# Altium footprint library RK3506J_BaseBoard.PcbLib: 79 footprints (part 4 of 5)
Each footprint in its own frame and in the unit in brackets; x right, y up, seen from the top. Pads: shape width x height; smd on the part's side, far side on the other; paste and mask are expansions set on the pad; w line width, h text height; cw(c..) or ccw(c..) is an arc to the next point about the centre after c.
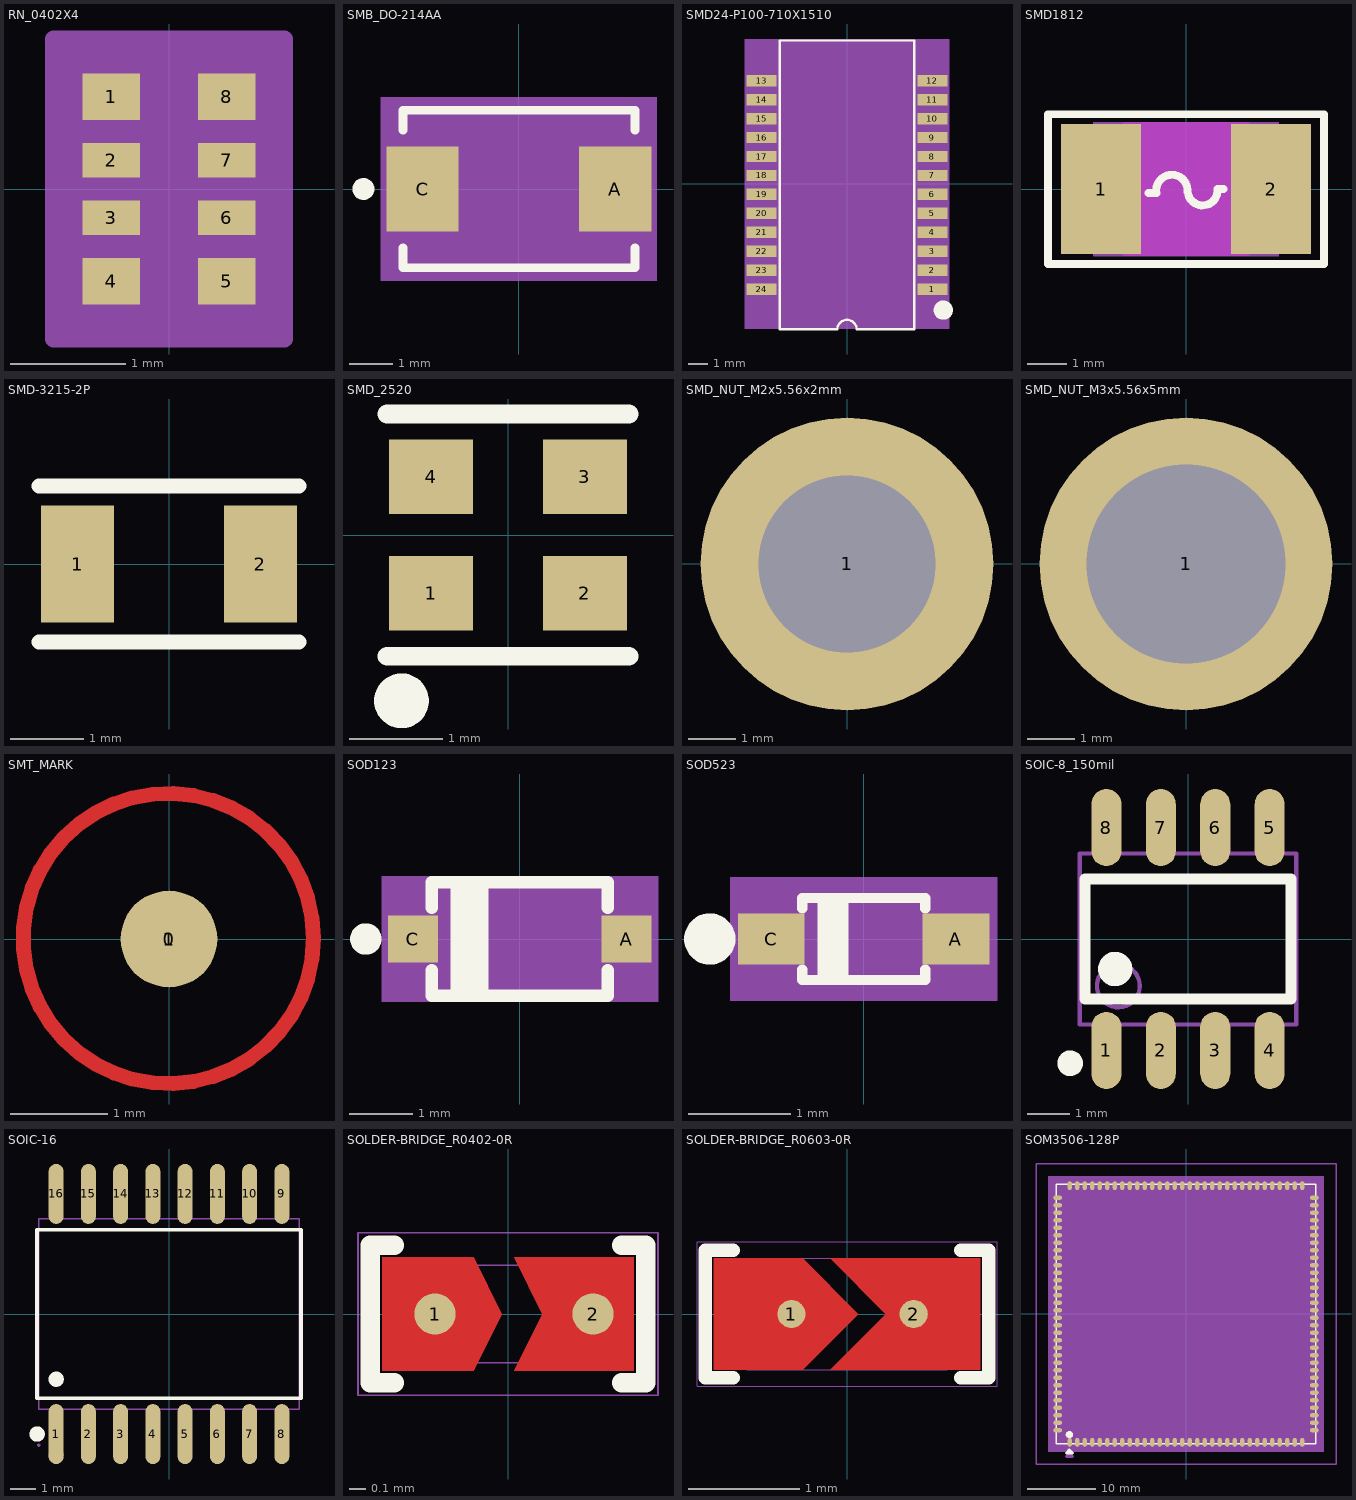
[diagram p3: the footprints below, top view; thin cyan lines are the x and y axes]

## RN_0402X4 [mm]
pads (8):
  rect 0.5x0.4 smd: 1(-0.5,0.8) 4(-0.5,-0.8) 5(0.5,-0.8) 8(0.5,0.8)
  rect 0.5x0.3 smd: 2(-0.5,0.25) 3(-0.5,-0.25) 6(0.5,-0.25) 7(0.5,0.25)
Top 3D Body:
  region: -1,1.3 -1,-1.3 1,-1.3 1,1.3
Top Assembly:
  lines w0.15: -1,-1.3 -1,1.3 1,1.3 1,-1.3 -1,-1.3
Top Courtyard:
  dashed: -1,1.3 -1,-1.3 1,-1.3 1,1.3
Mechanical 15:
  text "3" at -0.246,-0.25 h0.76
  text "1" at -0.246,0.8 h0.76
  text "4" at -0.246,-0.8 h0.76
  text "2" at -0.246,0.25 h0.76
  text "5" at 0.754,-0.8 h0.76
  text "8" at 0.754,0.8 h0.76
  text "6" at 0.754,-0.25 h0.76
  text "7" at 0.754,0.25 h0.76
3D body: height 3.81, standoff 0, extent -1,-1.3 1,1.3

## SMB_DO-214AA [mm]
pads (2):
  rect 1.65x1.95 smd: A(2.2,0) C(-2.2,0)
Top Overlay:
  circle w0.25: c-3.55,0 r0.125
  lines w0.2: -2.65,-1.35 -2.65,-1.8 2.65,-1.8 2.65,-1.35 ; -2.65,1.35 -2.65,1.8 2.65,1.8 2.65,1.35
Top 3D Body:
  circle w0.05: c0,0 r0.35
  region: -3.15,-2.1 -3.15,2.1 3.15,2.1 3.15,-2.1
  lines w0.05: -0.5,0 0.5,0 ; 0,-0.5 0,0.5
Top Assembly:
  lines w0.1: -2.568,-1.81 -2.568,1.81 ; -2.468,-1.81 -2.468,1.81 ; -2.368,-1.81 -2.368,1.81 ; -2.268,-1.81 -2.268,1.81 ; -2.168,-1.81 -2.168,1.81 ; -2.068,-1.81 -2.068,1.81 ; -1.968,-1.81 -1.968,1.81 ; -2.668,-1.81 -2.668,1.81 2.668,1.81 2.668,-1.81 -2.668,-1.81
Top Component Outline:
  lines w0.001: -2.795,-1.97 -2.795,1.97 2.795,1.97 2.795,-1.97 -2.795,-1.97
Top Courtyard:
  dashed: -3.15,-2.1 -3.15,2.1 3.15,2.1 3.15,-2.1
Mechanical 15:
  text "C" at -2.2,0.254 h0.76
  text "A" at 2.2,0.254 h0.76
3D body: height 3.81, standoff 0, extent -3.15,-2.1 3.15,2.1

## SMD24-P100-710X1510 [mm]
pads (24):
  rect 1.6x0.6 smd: 1(4.51,-5.55) 2(4.51,-4.55) 3(4.51,-3.55) 4(4.51,-2.55) 5(4.51,-1.55) 6(4.51,-0.55) 7(4.51,0.45) 8(4.51,1.45) 9(4.51,2.45) 10(4.51,3.45) 11(4.51,4.45) 12(4.51,5.45) 13(-4.51,5.45) 14(-4.51,4.45) 15(-4.51,3.45) 16(-4.51,2.45) 17(-4.51,1.45) 18(-4.51,0.45) 19(-4.51,-0.55) 20(-4.51,-1.55) 21(-4.51,-2.55) 22(-4.51,-3.55) 23(-4.51,-4.55) 24(-4.51,-5.55)
Top Overlay:
  circle w0.508: c5.08,-6.654 r0.254
  lines w0.127: -3.556,-7.67 -3.556,7.57 3.556,7.57 3.556,-7.67 0.508,-7.67 ccw(c0,-7.67) -0.508,-7.67 -3.556,-7.67
Top 3D Body:
  region: -5.4,-7.65 -5.4,7.65 5.4,7.65 5.4,-7.65
Top Assembly:
  circle w0.152: c2.794,-5.663 r0.402
  lines w0.051: -5,-7.6 -5,7.5 5,7.5 5,-7.6 -5,-7.6
Top Component Center:
  lines w0.051: -0.508,-0.05 0.508,-0.05 ; 0,-0.558 0,0.458
Mechanical 15:
  text "13" at -4.51,5.247 h0.25
  text "18" at -4.51,0.247 h0.25
  text "16" at -4.51,2.247 h0.25
  text "21" at -4.51,-2.753 h0.25
  text "22" at -4.51,-3.753 h0.25
  text "15" at -4.51,3.247 h0.25
  text "20" at -4.51,-1.753 h0.25
  text "19" at -4.51,-0.753 h0.25
  text "14" at -4.51,4.247 h0.25
  text "24" at -4.51,-5.753 h0.25
  text "23" at -4.51,-4.753 h0.25
  text "17" at -4.51,1.247 h0.25
  text "8" at 4.51,1.349 h0.25
  text "9" at 4.51,2.349 h0.25
  text "11" at 4.51,4.247 h0.25
  text "12" at 4.51,5.247 h0.25
  text "2" at 4.51,-4.652 h0.25
  text "3" at 4.51,-3.652 h0.25
  text "5" at 4.51,-1.652 h0.25
  text "6" at 4.51,-0.652 h0.25
  text "4" at 4.51,-2.652 h0.25
  text "10" at 4.51,3.247 h0.25
  text "1" at 4.51,-5.652 h0.25
  text "7" at 4.51,0.349 h0.25
3D body: height 3.81, standoff 0, extent -5.4,-7.65 5.4,7.65

## SMD1812 [mil]
pads (2):
  rect 80x130 smd: 1(-85,0) 2(85,0)
Top Layer keep-out:
  region: -63,66.9 -63,-66.9 63,-66.9 63,66.9
Top Overlay:
  lines w7.9: -37.4,-3.9 -29.5,-3.9 cw(c-14.1,-1.36) 1.5,-1.5 ; 1.6,-0.6 ccw(c16.57,-1.37) 31.5,0 37.4,0 ; -137.8,-74.8 -137.8,74.8 137.8,74.8 137.8,-74.8 -137.8,-74.8
Top 3D Body:
  region: -92.5,-66.9 -92.5,66.9 92.5,66.9 92.5,-66.9
Top Assembly:
  lines w1: -88.6,-63 -88.6,63 88.6,63 88.6,-63 -88.6,-63
Top Courtyard:
  lines w1: -92.5,-66.9 92.5,-66.9 92.5,66.9 -92.5,66.9 -92.5,-66.9
Top Component Center:
  lines w3: -20,0 20,0 ; 0,-20 0,20
Mechanical 15:
  text "1" at -95,0 h30
  text "2" at 75,0 h30
3D body: height 150, standoff 0, extent -92.5,-66.9 92.5,66.9

## SMD-3215-2P [mm]
pads (2):
  rect 1x1.6 smd mask+0.051: 1(-1.25,0) 2(1.25,0)
Top Overlay:
  lines w0.203: -1.778,-1.067 1.778,-1.067 ; -1.778,1.067 1.778,1.067

## SMD_2520 [mm]
pads (4):
  rect 0.9x0.8 smd: 1(-0.825,-0.625) 2(0.825,-0.625) 3(0.825,0.625) 4(-0.825,0.625)
Top Overlay:
  circle w0.305: c-1.143,-1.778 r0.141
  lines w0.203: -1.3,-1.3 1.3,-1.3 ; -1.3,1.3 1.3,1.3

## SMD_NUT_M2x5.56x2mm [mm]
pads (1):
  round 6.2 hole 3.75 mask+0.102: 1(0,0)
Top Paste:
  region: -1.097,1.803 -0.971,1.873 -0.707,1.988 -0.43,2.066 -0.144,2.105 0.144,2.105 0.429,2.066 0.706,1.988 0.97,1.874 1.096,1.803 1.862,2.569 1.863,2.571 1.661,2.717 1.217,2.943 0.742,3.097 0.249,3.175 -0.25,3.175 -0.742,3.097 -1.217,2.943 -1.662,2.717 -1.863,2.571
  region: 1.803,1.097 1.873,0.971 1.988,0.707 2.066,0.43 2.105,0.144 2.105,-0.144 2.066,-0.429 1.988,-0.706 1.874,-0.97 1.803,-1.096 2.569,-1.862 2.571,-1.863 2.717,-1.661 2.943,-1.217 3.097,-0.742 3.175,-0.249 3.175,0.25 3.097,0.742 2.943,1.217 2.717,1.662 2.571,1.863
  region: 1.097,-1.803 0.971,-1.873 0.707,-1.988 0.43,-2.066 0.144,-2.105 -0.144,-2.105 -0.429,-2.066 -0.706,-1.988 -0.97,-1.874 -1.096,-1.803 -1.862,-2.569 -1.863,-2.571 -1.661,-2.717 -1.217,-2.943 -0.742,-3.097 -0.249,-3.175 0.25,-3.175 0.742,-3.097 1.217,-2.943 1.662,-2.717 1.863,-2.571
  region: -1.803,-1.097 -1.873,-0.971 -1.988,-0.707 -2.066,-0.43 -2.105,-0.144 -2.105,0.144 -2.066,0.429 -1.988,0.706 -1.874,0.97 -1.803,1.096 -2.569,1.862 -2.571,1.863 -2.717,1.661 -2.943,1.217 -3.097,0.742 -3.175,0.249 -3.175,-0.25 -3.097,-0.742 -2.943,-1.217 -2.717,-1.662 -2.571,-1.863

## SMD_NUT_M3x5.56x5mm [mm]
pads (1):
  round 6.2 / inner round 5 / far side round 6.2 hole 4.22 mask+0.102: 1(0,0)
Top Paste:
  region: -1.097,1.803 -0.971,1.873 -0.707,1.988 -0.43,2.066 -0.144,2.105 0.144,2.105 0.429,2.066 0.706,1.988 0.97,1.874 1.096,1.803 1.862,2.569 1.863,2.571 1.661,2.717 1.217,2.943 0.742,3.097 0.249,3.175 -0.25,3.175 -0.742,3.097 -1.217,2.943 -1.662,2.717 -1.863,2.571
  region: 1.803,1.097 1.873,0.971 1.988,0.707 2.066,0.43 2.105,0.144 2.105,-0.144 2.066,-0.429 1.988,-0.706 1.874,-0.97 1.803,-1.096 2.569,-1.862 2.571,-1.863 2.717,-1.661 2.943,-1.217 3.097,-0.742 3.175,-0.249 3.175,0.25 3.097,0.742 2.943,1.217 2.717,1.662 2.571,1.863
  region: 1.097,-1.803 0.971,-1.873 0.707,-1.988 0.43,-2.066 0.144,-2.105 -0.144,-2.105 -0.429,-2.066 -0.706,-1.988 -0.97,-1.874 -1.096,-1.803 -1.862,-2.569 -1.863,-2.571 -1.661,-2.717 -1.217,-2.943 -0.742,-3.097 -0.249,-3.175 0.25,-3.175 0.742,-3.097 1.217,-2.943 1.662,-2.717 1.863,-2.571
  region: -1.803,-1.097 -1.873,-0.971 -1.988,-0.707 -2.066,-0.43 -2.105,-0.144 -2.105,0.144 -2.066,0.429 -1.988,0.706 -1.874,0.97 -1.803,1.096 -2.569,1.862 -2.571,1.863 -2.717,1.661 -2.943,1.217 -3.097,0.742 -3.175,0.249 -3.175,-0.25 -3.097,-0.742 -2.943,-1.217 -2.717,-1.662 -2.571,-1.863

## SMT_MARK [mm]
pads (2):
  round 3.1 on Top Solder: 0(0,0)
  round 1 smd: 1(0,0)
Top Layer:
  circle w0.152: c-0.007,0.005 r1.5

## SOD123 [mm]
pads (2):
  rect 0.8x0.75 smd: A(1.7,0) C(-1.7,0)
Top Overlay:
  circle w0.25: c-2.45,0 r0.125
  lines w0.2: -1.4,-0.5 -1.4,-0.9 1.4,-0.9 1.4,-0.5 ; -1.4,0.5 -1.4,0.9 1.4,0.9 1.4,0.5 ; -1,-0.8 -1,0.8 ; -0.8,-0.8 -0.8,0.8 ; -0.6,-0.8 -0.6,0.8
Top 3D Body:
  circle w0.05: c0,0 r0.35
  region: -2.2,-1 -2.2,1 2.2,1 2.2,-1
  lines w0.05: -0.5,0 0.5,0 ; 0,-0.5 0,0.5
Top Assembly:
  lines w0.1: -1.25,-0.8 -1.25,0.8 ; -1.15,-0.8 -1.15,0.8 ; -1.05,-0.8 -1.05,0.8 ; -0.95,-0.8 -0.95,0.8 ; -0.85,-0.8 -0.85,0.8 ; -0.75,-0.8 -0.75,0.8 ; -0.65,-0.8 -0.65,0.8 ; -1.35,-0.8 1.35,-0.8 1.35,0.8 -1.35,0.8 -1.35,-0.8
  text ".Designator" at -0.046,0.254 h0.36
Top Component Outline:
  lines w0.001: -1.425,-0.9 1.425,-0.9 1.425,0.9 -1.425,0.9 -1.425,-0.9
Top Courtyard:
  dashed: -2.2,-1 -2.2,1 2.2,1 2.2,-1
Mechanical 15:
  text "C" at -1.954,0 h0.64
  text "A" at 1.446,0 h0.64
3D body: height 3.81, standoff 0, extent -2.2,-1 2.2,1

## SOD523 [mm]
pads (2):
  rect 0.65x0.5 smd: A(0.9,0) C(-0.9,0)
Top Overlay:
  circle w0.25: c-1.5,0 r0.125
  lines w0.1: -0.6,-0.3 -0.6,-0.4 0.6,-0.4 0.6,-0.3 ; -0.6,0.3 -0.6,0.4 0.6,0.4 0.6,0.3 ; -0.4,-0.4 -0.4,0.4 ; -0.3,-0.4 -0.3,0.4 ; -0.2,-0.4 -0.2,0.4
Top 3D Body:
  circle w0.05: c0,0 r0.35
  region: -1.3,0.6 -1.3,-0.6 1.3,-0.6 1.3,0.6
  lines w0.05: -0.5,0 0.5,0 ; 0,-0.5 0,0.5
Top Assembly:
  lines w0.1: -0.475,-0.4 -0.475,0.4 ; -0.375,-0.4 -0.375,0.4 ; -0.275,-0.4 -0.275,0.4 ; -0.175,-0.4 -0.175,0.4 ; -0.075,-0.4 -0.075,0.4 ; -0.575,-0.4 0.575,-0.4 0.575,0.4 -0.575,0.4 -0.575,-0.4
  text ".Designator" at 0,-0.681 h0.36
Top Component Outline:
  lines w0.001: -0.6,-0.425 0.6,-0.425 0.6,0.425 -0.6,0.425 -0.6,-0.425
Mechanical 15:
  text "A" at 0.9,-0.254 h0.64
  text "C" at -0.9,-0.254 h0.64
3D body: height 3.81, standoff 0, extent -1.3,-0.6 1.3,0.6

## SOIC-8_150mil [mm]
pads (8):
  oval 0.7x1.8 smd: 1(-1.905,-2.6) 2(-0.635,-2.6) 3(0.635,-2.6) 4(1.905,-2.6) 5(1.905,2.6) 6(0.635,2.6) 7(-0.635,2.6) 8(-1.905,2.6)
Top Overlay:
  circle w0.4: c-1.7,-0.7 r0.2
  circle w0.3: c-2.75,-2.9 r0.15
  lines w0.254: -2.4,-1.4 -2.4,1.4 2.4,1.4 2.4,-1.4 -2.4,-1.4
Mechanical 13:
  circle w0.1: c-1.625,-1.095 r0.5
  lines w0.1: -2.525,-1.995 -2.525,1.995 2.525,1.995 2.525,-1.995 -2.525,-1.995

## SOIC-16 [mm]
pads (16):
  oval 0.595x2.36 smd: 1(-4.445,-4.73) 2(-3.175,-4.73) 3(-1.905,-4.73) 4(-0.635,-4.73) 5(0.635,-4.73) 6(1.905,-4.73) 7(3.175,-4.73) 8(4.445,-4.73) 9(4.445,4.73) 10(3.175,4.73) 11(1.905,4.73) 12(0.635,4.73) 13(-0.635,4.73) 14(-1.905,4.73) 15(-3.175,4.73) 16(-4.445,4.73)
Top Overlay:
  circle w0.3: c-4.445,-2.569 r0.15
  circle w0.3: c-5.195,-4.73 r0.15
  lines w0.152: -5.206,-3.321 -5.206,3.321 5.206,3.321 5.206,-3.321 -5.206,-3.321
Top Component Outline:
  circle w0.3: c-4.445,-5.563 r0.15
Mechanical 15:
  drawing of 37 lines, arcs and shapes, not listed

## SOLDER-BRIDGE_R0402-0R [mil]
pads (2):
  round 10 smd paste-393.7: 1(-17.72,0) 2(20.67,0)
Top Layer:
  region: -30.51,-13.78 -30.51,13.78 -8.37,13.78 -1.48,0 -8.37,-13.78
  region: 1.48,13.78 8.37,0 1.48,-13.78 30.51,-13.78 30.51,13.78
Top Overlay:
  lines w4.72: -27.56,-16.73 -33.46,-16.73 -33.46,16.73 -27.56,16.73 ; 27.56,-16.73 33.46,-16.73 33.46,16.73 27.56,16.73
Top Paste:
  rectangle: -27.56,-13.78 -8.37,13.78
  rectangle: 8.36,-13.78 27.55,13.78
Top Solder:
  region: -29.53,15.75 -6.4,15.75 1.48,0 -6.4,-15.75 -29.53,-15.75
  region: 5.41,0 -2.46,15.75 29.53,15.75 29.53,-15.75 -2.46,-15.75
Mechanical 14:
  lines w0.39: -17.72,-11.81 -17.72,11.81 17.72,11.81 17.72,-11.81 -17.72,-11.81
  text "'.Designator'" at -78.74,-19.68 h29.53
Mechanical 16:
  lines w0.39: -36.42,-19.68 -36.42,19.68 36.42,19.68 36.42,-19.68 -36.42,-19.68
3D body "R0402.STEP": height 13.39, standoff 0, extent -20.47,-11.81 20.47,11.81
3D body: height 13.78, standoff 0, extent -17.72,-11.81 17.72,11.81

## SOLDER-BRIDGE_R0603-0R [mil]
pads (2):
  round 10 smd paste-393.7: 1(-19.68,0) 2(23.62,0)
Top Layer:
  region: -47.24,-19.68 -47.24,19.68 -15.75,19.68 3.94,0 -15.75,-19.68
  region: -5.91,19.68 13.78,0 -5.91,-19.68 47.24,-19.68 47.24,19.68
Top Overlay:
  lines w4.72: -40.35,-22.64 -50.2,-22.64 -50.2,6.89 -50.2,22.64 -40.35,22.64 ; 40.35,-22.64 50.2,-22.64 50.2,22.64 40.35,22.64
Top Paste:
  rectangle: 14.96,-19.68 40.16,19.68
  rectangle: -40.16,-19.68 -14.96,19.69
Top Solder:
  region: -42.32,21.65 -14.76,21.65 6.89,0 -14.76,-21.65 -42.32,-21.65
  region: 10.83,0 -10.83,21.65 42.32,21.65 42.32,-21.65 -10.83,-21.65
Mechanical 14:
  lines w0.39: -35.43,-19.68 -35.43,19.68 35.43,19.68 35.43,-19.68 -35.43,-19.68
  text "'.Designator'" at -78.74,-19.68 h29.53
Mechanical 16:
  lines w0.39: -53.15,-25.59 -53.15,25.59 -7.87,25.59 53.15,25.59 53.15,-25.59 -53.15,-25.59
3D body "R0603.STEP": height 22.05, standoff 0, extent -33.46,-15.74 33.47,15.75
3D body: height 19.68, standoff 0, extent -35.63,-19.88 35.63,19.88

## SOM3506-128P [mm]
pads (128):
  oval 0.66x1.27 smd: 1(-17.05,-18.835) 2(-15.95,-18.835) 3(-14.85,-18.835) 4(-13.75,-18.835) 5(-12.65,-18.835) 6(-11.55,-18.835) 7(-10.45,-18.835) 8(-9.35,-18.835) 9(-8.25,-18.835) 10(-7.15,-18.835) 11(-6.05,-18.835) 12(-4.95,-18.835) 13(-3.85,-18.835) 14(-2.75,-18.835) 15(-1.65,-18.835) 16(-0.55,-18.835) 17(0.55,-18.835) 18(1.65,-18.835) 19(2.75,-18.835) 20(3.85,-18.835) 21(4.95,-18.835) 22(6.05,-18.835) 23(7.15,-18.835) 24(8.25,-18.835) 25(9.35,-18.835) 26(10.45,-18.835) 27(11.55,-18.835) 28(12.65,-18.835) 29(13.75,-18.835) 30(14.85,-18.835) 31(15.95,-18.835) 32(17.05,-18.835) 65(17.05,18.835) 66(15.95,18.835) 67(14.85,18.835) 68(13.75,18.835) 69(12.65,18.835) 70(11.55,18.835) 71(10.45,18.835) 72(9.35,18.835) 73(8.25,18.835) 74(7.15,18.835) 75(6.05,18.835) 76(4.95,18.835) 77(3.85,18.835) 78(2.75,18.835) 79(1.65,18.835) 80(0.55,18.835) 81(-0.55,18.835) 82(-1.65,18.835) 83(-2.75,18.835) 84(-3.85,18.835) 85(-4.95,18.835) 86(-6.05,18.835) 87(-7.15,18.835) 88(-8.25,18.835) 89(-9.35,18.835) 90(-10.45,18.835) 91(-11.55,18.835) 92(-12.65,18.835) 93(-13.75,18.835) 94(-14.85,18.835) 95(-15.95,18.835) 96(-17.05,18.835)
  oval 1.27x0.66 smd: 33(18.835,-17.05) 34(18.835,-15.95) 35(18.835,-14.85) 36(18.835,-13.75) 37(18.835,-12.65) 38(18.835,-11.55) 39(18.835,-10.45) 40(18.835,-9.35) 41(18.835,-8.25) 42(18.835,-7.15) 43(18.835,-6.05) 44(18.835,-4.95) 45(18.835,-3.85) 46(18.835,-2.75) 47(18.835,-1.65) 48(18.835,-0.55) 49(18.835,0.55) 50(18.835,1.65) 51(18.835,2.75) 52(18.835,3.85) 53(18.835,4.95) 54(18.835,6.05) 55(18.835,7.15) 56(18.835,8.25) 57(18.835,9.35) 58(18.835,10.45) 59(18.835,11.55) 60(18.835,12.65) 61(18.835,13.75) 62(18.835,14.85) 63(18.835,15.95) 64(18.835,17.05) 97(-18.835,17.05) 98(-18.835,15.95) 99(-18.835,14.85) 100(-18.835,13.75) 101(-18.835,12.65) 102(-18.835,11.55) 103(-18.835,10.45) 104(-18.835,9.35) 105(-18.835,8.25) 106(-18.835,7.15) 107(-18.835,6.05) 108(-18.835,4.95) 109(-18.835,3.85) 110(-18.835,2.75) 111(-18.835,1.65) 112(-18.835,0.55) 113(-18.835,-0.55) 114(-18.835,-1.65) 115(-18.835,-2.75) 116(-18.835,-3.85) 117(-18.835,-4.95) 118(-18.835,-6.05) 119(-18.835,-7.15) 120(-18.835,-8.25) 121(-18.835,-9.35) 122(-18.835,-10.45) 123(-18.835,-11.55) 124(-18.835,-12.65) 125(-18.835,-13.75) 126(-18.835,-14.85) 127(-18.835,-15.95) 128(-18.835,-17.05)
Top Overlay:
  dashed: -17.1,-18.21 -16.905,-18.171 -16.74,-18.06 -16.629,-17.895 -16.59,-17.7 -16.629,-17.505 -16.666,-17.449 -16.74,-17.34 -16.905,-17.229 -17.1,-17.19 -17.295,-17.229 -17.46,-17.34 -17.534,-17.449 -17.571,-17.505 -17.61,-17.7 -17.571,-17.895 -17.46,-18.06 -17.295,-18.171
  lines w0.2: -19,-19 -19,19 19,19 19,-19 -19,-19
  lines w0.5: -17.5,-20.392 -16.7,-20.392 -17.1,-19.992 -17.5,-20.392
Top 3D Body:
  region: -20.2,-20.2 -20.2,20.2 20.2,20.2 20.2,-20.2
Top Assembly:
  dashed: -17.1,-18.21 -16.905,-18.171 -16.74,-18.06 -16.629,-17.895 -16.59,-17.7 -16.629,-17.505 -16.666,-17.449 -16.74,-17.34 -16.905,-17.229 -17.1,-17.19 -17.295,-17.229 -17.46,-17.34 -17.534,-17.449 -17.571,-17.505 -17.61,-17.7 -17.571,-17.895 -17.46,-18.06 -17.295,-18.171
  lines w0.2: -22,-22 -22,22 22,22 22,-22 -22,-22 ; -19,-19 -19,19 19,19 19,-19 -19,-19
  lines w0.5: -17.5,-20.9 -16.7,-20.9 -17.1,-20.5 -17.5,-20.9
Mechanical 15:
  text "16" at 0.72,-17.819 h0.76
  text "93" at -15.02,19.851 h0.76
  text "39" at 18.835,-8.164 h0.76
  text "24" at 9.52,-17.819 h0.76
  text "22" at 7.32,-17.819 h0.76
  text "40" at 18.835,-7.064 h0.76
  text "18" at 2.92,-17.819 h0.76
  text "19" at 4.02,-17.819 h0.76
  text "50" at 18.835,3.936 h0.76
  text "45" at 18.835,-1.564 h0.76
  text "14" at -1.48,-17.819 h0.76
  text "41" at 18.835,-5.964 h0.76
  text "27" at 12.82,-17.819 h0.76
  text "28" at 13.92,-17.819 h0.76
  text "29" at 15.02,-17.819 h0.76
  text "20" at 5.12,-17.819 h0.76
  text "30" at 16.12,-17.819 h0.76
  text "31" at 17.22,-17.819 h0.76
  text "36" at 18.835,-11.464 h0.76
  text "21" at 6.22,-17.819 h0.76
  text "63" at 18.835,18.236 h0.76
  text "13" at -2.58,-17.819 h0.76
  text "85" at -6.22,19.851 h0.76
  text "86" at -7.32,19.851 h0.76
  text "64" at 18.835,19.336 h0.76
  text "117" at -18.835,-4.696 h0.76
  text "128" at -18.835,-16.796 h0.76
  text "78" at 1.48,19.851 h0.76
  text "79" at 0.38,19.851 h0.76
  text "80" at -0.72,19.851 h0.76
  text "77" at 2.58,19.851 h0.76
  text "76" at 3.68,19.851 h0.76
  text "81" at -1.82,19.851 h0.76
  text "7" at -9.18,-18.327 h0.76
  text "8" at -8.08,-18.327 h0.76
  text "9" at -6.98,-18.327 h0.76
  text "89" at -10.62,19.851 h0.76
  text "88" at -9.52,19.851 h0.76
  text "26" at 11.72,-17.819 h0.76
  text "84" at -5.12,19.851 h0.76
  text "83" at -4.02,19.851 h0.76
  text "68" at 12.48,19.851 h0.76
  text "119" at -18.835,-6.896 h0.76
  text "118" at -18.835,-5.796 h0.76
  text "6" at -10.28,-18.327 h0.76
  text "4" at -12.48,-18.327 h0.76
  text "3" at -13.58,-18.327 h0.76
  text "2" at -14.68,-18.327 h0.76
  text "1" at -15.78,-18.327 h0.76
  text "125" at -18.835,-13.496 h0.76
  text "123" at -18.835,-11.296 h0.76
  text "122" at -18.835,-10.196 h0.76
  text "121" at -18.835,-9.096 h0.76
  text "120" at -18.835,-7.996 h0.76
  text "116" at -18.835,-3.596 h0.76
  text "114" at -18.835,-1.396 h0.76
  text "113" at -18.835,-0.296 h0.76
  text "112" at -18.835,0.804 h0.76
  text "111" at -18.835,1.904 h0.76
  text "109" at -18.835,4.104 h0.76
  text "108" at -18.835,5.204 h0.76
  text "107" at -18.835,6.304 h0.76
  text "106" at -18.835,7.404 h0.76
  text "33" at 18.835,-14.764 h0.76
  text "34" at 18.835,-13.664 h0.76
  text "127" at -18.835,-15.696 h0.76
  text "126" at -18.835,-14.596 h0.76
  text "46" at 18.835,-0.464 h0.76
  text "11" at -4.78,-17.819 h0.76
  text "25" at 10.62,-17.819 h0.76
  text "42" at 18.835,-4.864 h0.76
  text "94" at -16.12,19.851 h0.76
  text "62" at 18.835,17.136 h0.76
  text "69" at 11.38,19.851 h0.76
  text "70" at 10.28,19.851 h0.76
  text "71" at 9.18,19.851 h0.76
  text "74" at 5.88,19.851 h0.76
  text "72" at 8.08,19.851 h0.76
  text "73" at 6.98,19.851 h0.76
  text "102" at -18.835,11.804 h0.76
  text "96" at -18.32,19.851 h0.76
  text "95" at -17.22,19.851 h0.76
  text "91" at -12.82,19.851 h0.76
  text "92" at -13.92,19.851 h0.76
  text "58" at 18.835,12.736 h0.76
  text "55" at 18.835,9.436 h0.76
  text "56" at 18.835,10.536 h0.76
  text "53" at 18.835,7.236 h0.76
  text "57" at 18.835,11.636 h0.76
  text "54" at 18.835,8.336 h0.76
  text "51" at 18.835,5.036 h0.76
  text "99" at -18.835,14.596 h0.76
  text "52" at 18.835,6.136 h0.76
  text "98" at -18.835,15.696 h0.76
  text "101" at -18.835,12.904 h0.76
  text "104" at -18.835,9.604 h0.76
  text "103" at -18.835,10.704 h0.76
  text "38" at 18.835,-9.264 h0.76
  text "47" at 18.835,0.636 h0.76
  text "37" at 18.835,-10.364 h0.76
  text "49" at 18.835,2.836 h0.76
  text "59" at 18.835,13.836 h0.76
  text "60" at 18.835,14.936 h0.76
  text "43" at 18.835,-3.764 h0.76
  text "66" at 14.68,19.851 h0.76
  text "65" at 15.78,19.851 h0.76
  text "32" at 18.32,-17.819 h0.76
  text "67" at 13.58,19.851 h0.76
  text "75" at 4.78,19.851 h0.76
  text "100" at -18.835,14.004 h0.76
  text "115" at -18.835,-2.496 h0.76
  text "97" at -18.835,16.796 h0.76
  text "105" at -18.835,8.504 h0.76
  text "110" at -18.835,3.004 h0.76
  text "124" at -18.835,-12.396 h0.76
  text "5" at -11.38,-18.327 h0.76
  text "90" at -11.72,19.851 h0.76
  text "87" at -8.42,19.851 h0.76
  text "10" at -5.88,-17.819 h0.76
  text "12" at -3.68,-17.819 h0.76
  text "82" at -2.92,19.851 h0.76
  text "15" at -0.38,-17.819 h0.76
  text "17" at 1.82,-17.819 h0.76
  text "23" at 8.42,-17.819 h0.76
  text "61" at 18.835,16.036 h0.76
  text "48" at 18.835,1.736 h0.76
  text "44" at 18.835,-2.664 h0.76
  text "35" at 18.835,-12.564 h0.76
3D body "rc3506.STEP": height 2.63, standoff 0.03, extent -19.723,-19.723 19.877,19.877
